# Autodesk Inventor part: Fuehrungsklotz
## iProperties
Created: 2006-11
Part Number: Fuehrungsklotz
Cost Center: 0,304 kg
Material: Nylon - 6/6
Document SubType Name: Modeling
Designer: Schmidt
Authority: 269081 mm^3
Density: 1.13 g/cm^3
SaveDate: 2006-11-03
SaveTime: 01:04
TotalMass: 0,304 kg
TotalVolume: 269081 mm^3
Author: Schmidt
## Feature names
1. Extrusion2
2. Extrusion3
3. Zapfen Ø13 mm x 7 mm tief, Ø7 mm durch_1 [Hole]
4. Rechteckige Anordnung1 [Rectangular Pattern]
5. Extrusion4
6. Radius 5 mm_1 [Fillet]
